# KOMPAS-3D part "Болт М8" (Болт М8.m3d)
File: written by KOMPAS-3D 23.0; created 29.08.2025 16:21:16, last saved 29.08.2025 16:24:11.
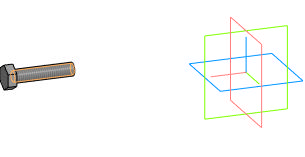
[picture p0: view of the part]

Document properties: Автор: Inspektor_Kot; Полное имя файла: I:\Autodesk Inventor Projects\ИМ-ИТ ЦД\Вариант 4\Болт М8.m3d

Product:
- Part/product: Болт М8
    Масса: 0.02031

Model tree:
1. Эскиз:1  (with: Элемент выдавливания:1)  (labels: Болт М8)
2. Элемент выдавливания:1  (labels: Болт М8)
     Расстояние 1 = 36
3. Эскиз:2  (with: Элемент выдавливания:1)
4. Элемент выдавливания:2
     Расстояние 1 = 5.3
5. Условное изображение резьбы:1  (with: Элемент выдавливания:1, Элемент выдавливания:2)  (labels: M8; cil0_24705-2004 coarse)
     Длина резьбы = 36; Шаг резьбы = 1.25; Номинальный диаметр резьбы = 8
6. Подгонка:1  (with: Элемент выдавливания:1)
